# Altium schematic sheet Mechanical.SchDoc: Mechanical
size A4; Date: Not used; ApprovedBy: Not used; CheckedBy: Not used; Author: Not used; CompanyName: STMicroelectronics; DrawnBy: Not used; Engineer: Not used; Organization: Not used; Address1: Not used; Address2: Not used; Address3: Not used; Address4: Not used; DocumentNumber: Not used; Revision: Not used; SheetNumber: 6; SheetTotal: 6
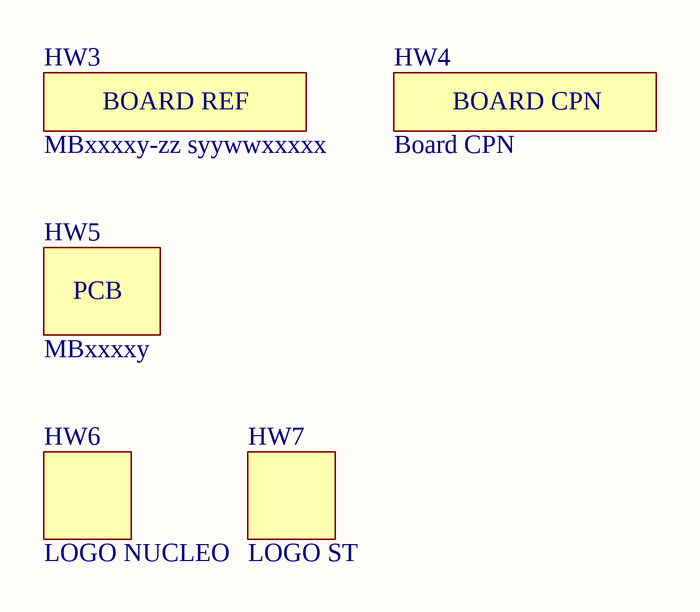
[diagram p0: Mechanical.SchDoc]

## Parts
HW3  value MBxxxxy-zz syywwxxxxx  [STICKER_25X9]  (hidden comment: STICKER_BOARD_REF)  (mechanical)
HW4  value Board CPN  [STICKER_25X9]  (hidden comment: STICKER_BOARD_CPN)  (mechanical)
HW5  value MBxxxxy  (hidden comment: PCB)  (mechanical)
HW6  value LOGO NUCLEO  [LOGO_NUCLEO]  (hidden comment: Logo)  (no BOM)
HW7  value LOGO ST  [LOGO_ST]  (hidden comment: Logo)  (no BOM)

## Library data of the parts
HW3 = MCD-00235: Sticker to mention board reference + serial number; Part_Type: Mechanical; Provided_By: SUBCO
HW4 = MCD-00547: Sticker to mention board CPN code; Part_Type: Mechanical; Provided_By: SUBCO
HW5 = MCD-00216: PCB, xxxx for PCB number, Y for PCB revision; Part_Type: Mechanical; Provided_By: SUBCO
HW6 = MCD-00636: NUCLEO logo footprint for PCB; Part_Type: Mechanical
HW7 = MCD-00625: STMicroelectronics logo footprint for PCB; Part_Type: Mechanical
